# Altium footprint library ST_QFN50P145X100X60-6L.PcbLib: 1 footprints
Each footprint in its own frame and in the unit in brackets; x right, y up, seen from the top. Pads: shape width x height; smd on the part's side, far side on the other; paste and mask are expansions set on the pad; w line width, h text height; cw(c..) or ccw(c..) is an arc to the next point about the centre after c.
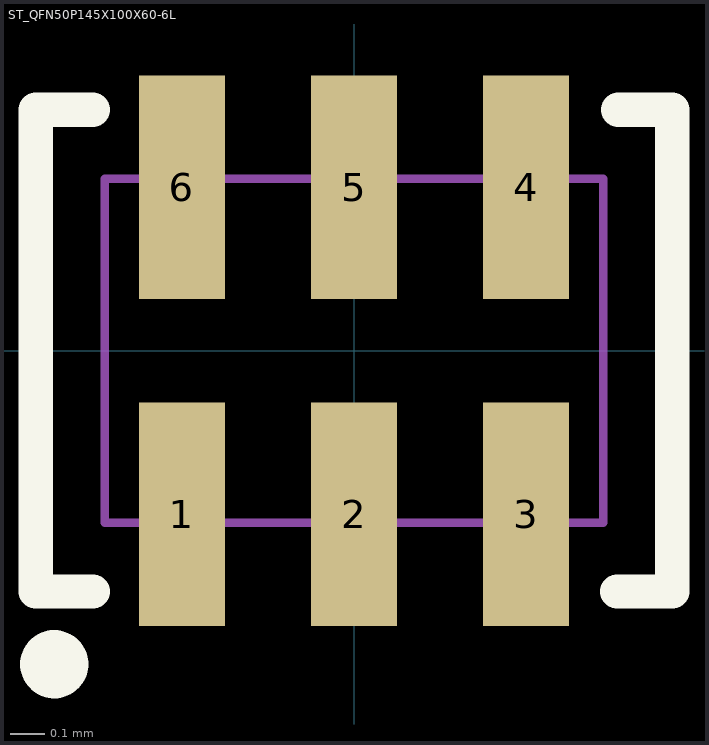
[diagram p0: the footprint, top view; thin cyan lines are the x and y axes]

## ST_QFN50P145X100X60-6L [mm] "ST_QFN50P145X100X60-6L"
pads (6):
  rect 0.25x0.65 smd paste-20 mask+0.05: 1(-0.5,-0.475) 2(0,-0.475) 3(0.5,-0.475) 4(0.5,0.475) 5(0,0.475) 6(-0.5,0.475)
Top Overlay:
  circle w0.15: c-0.872,-0.912 r0.024
  lines w0.1: -0.76,-0.7 -0.925,-0.7 -0.925,0.7 -0.76,0.7 ; 0.765,-0.7 0.925,-0.7 0.925,0.7 0.768,0.7
Top Paste:
  rectangle: 0.38,-0.785 0.62,-0.165
  rectangle: -0.12,-0.785 0.12,-0.165
  rectangle: -0.62,-0.785 -0.38,-0.165
  rectangle: 0.38,0.165 0.62,0.785
  rectangle: -0.12,0.165 0.12,0.785
  rectangle: -0.62,0.165 -0.38,0.785
Mechanical 5:
  text "4" at 0.445,0.94 h0.05
  text "6" at -0.555,0.94 h0.05
  text "5" at -0.055,0.94 h0.05
  text "2" at -0.03,-1 h0.05
  text "1" at -0.53,-1 h0.05
  text "3" at 0.47,-1 h0.05
Mechanical 6:
  lines w0.025: -0.725,-0.5 -0.725,0.5 0.725,0.5 0.725,-0.5 -0.725,-0.5
Assembly:
  lines w0.025: -0.725,-0.5 0.725,-0.5 0.725,0.5 -0.725,0.5 -0.725,-0.5
3D body: height 0.6, standoff 0, extent -0.725,-0.5 0.725,0.5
